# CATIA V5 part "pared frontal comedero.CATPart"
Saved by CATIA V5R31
Part number: pared frontal comedero
Bounding box of the stored display mesh (mm): x -124.2 to 124.2, y -32.8 to 29.5, z 0 to 3.3
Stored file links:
  C:\Users\189361\Desktop\pared frontal comedero.CATPart
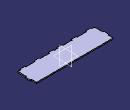
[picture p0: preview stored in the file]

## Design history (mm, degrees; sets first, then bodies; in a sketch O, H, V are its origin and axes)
Set1 "sketch"
  Sketch1 on xy-plane, origin (0, 0, 0), H (1, 0, 0), V (0, 1, 0)
    point P1 (0, 29.5)
    line L1 (0, 29.5) -> (-120.9, 29.5)
    point P2 (-120.9, 29.5)
    line L2 (-120.9, 29.5) -> (-120.9, 13.4)
    point P3 (-120.9, -29.5)
    point P4 (-95.65, -32.8)
    line L3 (-95.65, -32.8) -> (-95.65, -29.5)
    point P5 (-95.65, -29.5)
    line L4 (-95.65, -29.5) -> (-66.45, -29.5)
    point P6 (-66.45, -29.5)
    line L5 (-66.45, -29.5) -> (-66.45, -32.8)
    point P7 (-66.45, -32.8)
    line L6 (-66.45, -32.8) -> (-50.65, -32.8)
    point P8 (-50.65, -32.8)
    line L7 (-50.65, -32.8) -> (-50.65, -29.5)
    point P9 (-50.65, -29.5)
    line L8 (-50.65, -29.5) -> (-21.45, -29.5)
    point P10 (-21.45, -29.5)
    line L9 (-21.45, -29.5) -> (-21.45, -32.8)
    point P11 (-21.45, -32.8)
    line L10 (-21.45, -32.8) -> (-5.65, -32.8)
    point P12 (-5.65, -32.8)
    line L11 (-5.65, -32.8) -> (-5.65, -29.5)
    point P13 (-5.65, -29.5)
    line L12 (-5.65, -29.5) -> (0, -29.5)
    point P14 (0, -29.5)
    line L13 (-120.9, -29.5) -> (-111.45, -29.5)
    point P15 (-111.45, -29.5)
    line L14 (-111.45, -29.5) -> (-111.45, -32.8)
    point P16 (-111.45, -32.8)
    line L15 (-111.45, -32.8) -> (-95.65, -32.8)
    point P17 (-124.2, -2.4)
    line L16 (-124.2, -2.4) -> (-124.2, 13.4)
    point P18 (-124.2, 13.4)
    line L17 (-124.2, 13.4) -> (-120.9, 13.4)
    point P19 (-120.9, 13.4)
    line L18 (-124.2, -2.4) -> (-120.9, -2.4)
    point P20 (-120.9, -2.4)
    line L19 (-120.9, -2.4) -> (-120.9, -29.5)
    construction line L20 (-137.9355, 5.5) -> (-107.3097, 5.5)
    point P22 (-107.3097, 5.5)
    point P23 (120.9, 29.5)
    point P24 (120.9, -29.5)
    point P25 (95.65, -32.8)
    point P26 (95.65, -29.5)
    point P27 (66.45, -29.5)
    point P28 (66.45, -32.8)
    point P29 (50.65, -32.8)
    point P30 (50.65, -29.5)
    point P31 (21.45, -29.5)
    point P32 (21.45, -32.8)
    point P33 (5.65, -32.8)
    point P34 (5.65, -29.5)
    point P35 (111.45, -29.5)
    point P36 (111.45, -32.8)
    point P37 (124.2, -2.4)
    point P38 (124.2, 13.4)
    point P39 (120.9, 13.4)
    point P40 (120.9, -2.4)
    point P41 (107.3097, 5.5)
    line L21 (120.9, 29.5) -> (120.9, 13.4)
    line L22 (95.65, -32.8) -> (95.65, -29.5)
    line L23 (95.65, -29.5) -> (66.45, -29.5)
    line L24 (66.45, -29.5) -> (66.45, -32.8)
    line L25 (66.45, -32.8) -> (50.65, -32.8)
    line L26 (50.65, -32.8) -> (50.65, -29.5)
    line L27 (50.65, -29.5) -> (21.45, -29.5)
    line L28 (21.45, -29.5) -> (21.45, -32.8)
    line L29 (21.45, -32.8) -> (5.65, -32.8)
    line L30 (5.65, -32.8) -> (5.65, -29.5)
    line L31 (120.9, -29.5) -> (111.45, -29.5)
    line L32 (111.45, -29.5) -> (111.45, -32.8)
    line L33 (111.45, -32.8) -> (95.65, -32.8)
    line L34 (124.2, -2.4) -> (124.2, 13.4)
    line L35 (124.2, 13.4) -> (120.9, 13.4)
    line L36 (124.2, -2.4) -> (120.9, -2.4)
    line L37 (120.9, -2.4) -> (120.9, -29.5)
    point P42 (0, -29.5)
    line L38 (5.65, -29.5) -> (0, -29.5)
    point P43 (0, 29.5)
    line L39 (0, 29.5) -> (120.9, 29.5)
    construction line L40 (0, -9.1884) -> (-6.05, -9.1884)
    point P44 (0, -9.1884)
    point P45 (-6.05, -9.1884)
    construction line L41 (-6.05, -9.1884) -> (-21.05, -9.1884)
    point P46 (-21.05, -9.1884)
    construction line L42 (-21.05, -9.1884) -> (-51.05, -9.1884)
    construction line L43 (-51.05, -9.1884) -> (-66.05, -9.1884)
    point P48 (-66.05, -9.1884)
    construction line L44 (-66.05, -9.1884) -> (-96.05, -9.1884)
    axis line L45 (-96.05, -9.1884) -> (-111.05, -9.1884)
    point P50 (-111.05, -9.1884)
    length L4 = 29.2
    length L3 = 3.3
    distance V L2 = 120.9
    distance H L1 = 29.5
    distance P2 P3 = 59
    length L17 = 3.3
    distance L20 L13 = 35
    distance L20 L17 = 7.9
    distance L20 L18 = 7.9
    length L8 = 29.2
    length L40 = 6.05
    length L41 = 15
    length L42 = 30
    length L43 = 15
    length L44 = 30
    length L45 = 15
    distance P45 L11 = 0.4
    distance L9 P46 = 0.4
    distance L5 P48 = 0.4
    distance L14 P50 = 0.4
    distance L11 V = 5.65 (reference)
    horizontal: L1 H, L4 H, L6 H, L8 H, L10 H, L12 H, L13 H, L15 H, L17 H, L18 H, L20 H, L40 H, L41 H, L42 H, L43 H, L44 H, L45 H
    vertical: L2 V, L3 V, L5 V, L7 V, L9 V, L11 V, L14 V, L16 V, L19 V
    coincidence: P9 L4, P13 L4, P14 V, P1 V, P3 L4, P16 L6, P20 L2, L2 L19, P1 P43, P14 P42, P44 V
    equal size: L3 L5, L5 L7, L7 L9, L9 L11
    symmetry: P2 P23 V, P3 P24 V, P4 P25 V, P5 P26 V, P6 P27 V, P7 P28 V, P8 P29 V, P9 P30 V, P10 P31 V, P11 P32 V, P12 P33 V, P13 P34 V, P15 P35 V, P16 P36 V, P17 P37 V, P18 P38 V, P19 P39 V, P20 P40 V, P22 P41 V, L2 L21 V, L3 L22 V, L4 L23 V, L5 L24 V, L6 L25 V, L7 L26 V, L8 L27 V, L9 L28 V, L10 L29 V, L11 L30 V, L13 L31 V, L14 L32 V, L15 L33 V, L16 L34 V, L17 L35 V, L18 L36 V, L19 L37 V, P14 P42 V, L12 L38 V, P1 P43 V, L1 L39 V
Body1 (main body)
  Pad1: profile Sketch1, direction (0, 0, 1), length 3.3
